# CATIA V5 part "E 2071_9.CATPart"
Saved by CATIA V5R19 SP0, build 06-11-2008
Definition: E 2071_9
Nomenclature: E 2071_9
Description: PART-E 2071_9-DESC
Material "Steel": density 7860 kg/m3, Young's modulus 2e+11 Pa, Poisson ratio 0.266, thermal expansion 1.17e-05 1/K
Bounding box of the stored display mesh (mm): x 437 to 446, y -4.5 to 4.5, z 0 to 10
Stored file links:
  G:\UTB\Kombinované\Bakalářská práce\Catia\FORMA\E 2071_9.CATPart
  D:\Aplikace\CATIA\Nová složka\win_b64\startup\materials\Catalog.CATMaterial
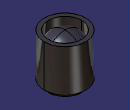
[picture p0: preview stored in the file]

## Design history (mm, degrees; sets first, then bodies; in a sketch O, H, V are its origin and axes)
Body1 "E 2071_9" (main body)
  Solid1: solid without history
